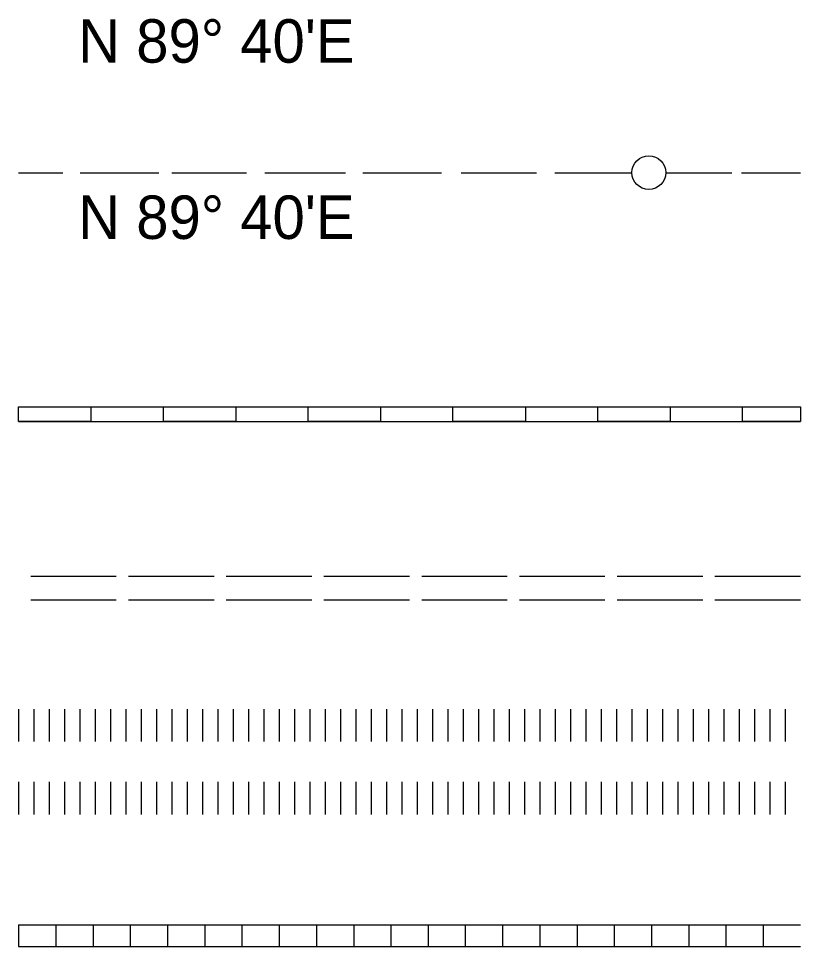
# Model space of a CAD drawing. Extents: x 49991.4 to 50021, y 49987.6 to 50011.4.
# Drawn here: x 50003.971 to 50005.051, y 49992.2 to 49993.482 of the extents above; entities that cross this region are included whole.
import ezdxf

# ---------------------------------------------------------------- set-up
doc = ezdxf.new("R2010")
doc.units = 0
doc.layers.add('Level 1', color=7, linetype='Continuous')
doc.layers.add('Level 2', color=7, linetype='Continuous')

msp = doc.modelspace()

# ---------------------------------------------------------------- linework, layer by layer
at = {"layer": 'Level 1'}
for p, q in [((50003.9708, 49993.2685), (50004.0321, 49993.2685)), ((50004.0559, 49993.2685), (50004.1647, 49993.2685)), ((50004.1826, 49993.2685), (50004.2855, 49993.2685)), ((50004.3108, 49993.2685), (50004.4226, 49993.2685)), ((50004.4464, 49993.2685), (50004.5552, 49993.2685)), ((50004.582, 49993.2685), (50004.6864, 49993.2685)), ((50004.7117, 49993.2685), (50004.818, 49993.2685)), ((50004.8647, 49993.2685), (50004.9561, 49993.2685)), ((50004.9695, 49993.2685), (50005.0508, 49993.2685)), ((50003.9708, 49992.9453), (50005.0508, 49992.9453)), ((50003.9708, 49992.9253), (50005.0508, 49992.9253)), ((50003.9877, 49992.7118), (50004.1058, 49992.7118)), ((50004.1227, 49992.7118), (50004.2408, 49992.7118)), ((50004.2577, 49992.7118), (50004.3758, 49992.7118)), ((50004.3927, 49992.7118), (50004.5108, 49992.7118)), ((50004.5277, 49992.7118), (50004.6458, 49992.7118)), ((50004.6627, 49992.7118), (50004.7808, 49992.7118)), ((50004.7977, 49992.7118), (50004.9158, 49992.7118)), ((50004.9327, 49992.7118), (50005.0508, 49992.7118)), ((50003.9877, 49992.6788), (50004.1058, 49992.6788)), ((50004.1227, 49992.6788), (50004.2408, 49992.6788)), ((50004.2577, 49992.6788), (50004.3758, 49992.6788)), ((50004.3927, 49992.6788), (50004.5108, 49992.6788)), ((50004.5277, 49992.6788), (50004.6458, 49992.6788)), ((50004.6627, 49992.6788), (50004.7808, 49992.6788)), ((50004.7977, 49992.6788), (50004.9158, 49992.6788)), ((50004.9327, 49992.6788), (50005.0508, 49992.6788)), ((50003.9708, 49992.5281), (50003.9708, 49992.4831)), ((50003.992, 49992.5281), (50003.992, 49992.4831)), ((50004.0131, 49992.5281), (50004.0131, 49992.4831)), ((50004.0343, 49992.5281), (50004.0343, 49992.4831)), ((50004.0555, 49992.5281), (50004.0555, 49992.4831)), ((50004.0767, 49992.5281), (50004.0767, 49992.4831)), ((50004.0978, 49992.5281), (50004.0978, 49992.4831)), ((50004.119, 49992.5281), (50004.119, 49992.4831)), ((50004.1402, 49992.5281), (50004.1402, 49992.4831)), ((50004.1614, 49992.5281), (50004.1614, 49992.4831)), ((50004.1826, 49992.5281), (50004.1826, 49992.4831)), ((50004.2037, 49992.5281), (50004.2037, 49992.4831)), ((50004.2249, 49992.5281), (50004.2249, 49992.4831)), ((50004.2461, 49992.5281), (50004.2461, 49992.4831)), ((50004.2673, 49992.5281), (50004.2673, 49992.4831)), ((50004.2884, 49992.5281), (50004.2884, 49992.4831)), ((50004.3096, 49992.5281), (50004.3096, 49992.4831)), ((50004.3308, 49992.5281), (50004.3308, 49992.4831)), ((50004.3308, 49992.5281), (50004.3308, 49992.4831)), ((50004.352, 49992.5281), (50004.352, 49992.4831)), ((50004.3731, 49992.5281), (50004.3731, 49992.4831)), ((50004.3943, 49992.5281), (50004.3943, 49992.4831)), ((50004.4155, 49992.5281), (50004.4155, 49992.4831)), ((50004.4367, 49992.5281), (50004.4367, 49992.4831)), ((50004.4578, 49992.5281), (50004.4578, 49992.4831)), ((50004.479, 49992.5281), (50004.479, 49992.4831)), ((50004.5002, 49992.5281), (50004.5002, 49992.4831)), ((50004.5214, 49992.5281), (50004.5214, 49992.4831)), ((50004.5426, 49992.5281), (50004.5426, 49992.4831)), ((50004.5637, 49992.5281), (50004.5637, 49992.4831)), ((50004.5849, 49992.5281), (50004.5849, 49992.4831)), ((50004.6061, 49992.5281), (50004.6061, 49992.4831)), ((50004.6273, 49992.5281), (50004.6273, 49992.4831)), ((50004.6484, 49992.5281), (50004.6484, 49992.4831)), ((50004.6696, 49992.5281), (50004.6696, 49992.4831)), ((50004.6908, 49992.5281), (50004.6908, 49992.4831)), ((50004.6908, 49992.5281), (50004.6908, 49992.4831)), ((50004.712, 49992.5281), (50004.712, 49992.4831)), ((50004.7331, 49992.5281), (50004.7331, 49992.4831)), ((50004.7543, 49992.5281), (50004.7543, 49992.4831)), ((50004.7755, 49992.5281), (50004.7755, 49992.4831)), ((50004.7967, 49992.5281), (50004.7967, 49992.4831)), ((50004.8178, 49992.5281), (50004.8178, 49992.4831)), ((50004.839, 49992.5281), (50004.839, 49992.4831)), ((50004.8602, 49992.5281), (50004.8602, 49992.4831)), ((50004.8814, 49992.5281), (50004.8814, 49992.4831)), ((50004.9026, 49992.5281), (50004.9026, 49992.4831)), ((50004.9237, 49992.5281), (50004.9237, 49992.4831)), ((50004.9449, 49992.5281), (50004.9449, 49992.4831)), ((50004.9661, 49992.5281), (50004.9661, 49992.4831)), ((50004.9873, 49992.5281), (50004.9873, 49992.4831)), ((50005.0084, 49992.5281), (50005.0084, 49992.4831)), ((50005.0296, 49992.5281), (50005.0296, 49992.4831)), ((50003.9708, 49992.4276), (50003.9708, 49992.3826)), ((50003.992, 49992.4276), (50003.992, 49992.3826)), ((50004.0131, 49992.4276), (50004.0131, 49992.3826)), ((50004.0343, 49992.4276), (50004.0343, 49992.3826)), ((50004.0555, 49992.4276), (50004.0555, 49992.3826)), ((50004.0767, 49992.4276), (50004.0767, 49992.3826)), ((50004.0978, 49992.4276), (50004.0978, 49992.3826)), ((50004.119, 49992.4276), (50004.119, 49992.3826)), ((50004.1402, 49992.4276), (50004.1402, 49992.3826)), ((50004.1614, 49992.4276), (50004.1614, 49992.3826)), ((50004.1826, 49992.4276), (50004.1826, 49992.3826)), ((50004.2037, 49992.4276), (50004.2037, 49992.3826)), ((50004.2249, 49992.4276), (50004.2249, 49992.3826)), ((50004.2461, 49992.4276), (50004.2461, 49992.3826)), ((50004.2673, 49992.4276), (50004.2673, 49992.3826)), ((50004.2884, 49992.4276), (50004.2884, 49992.3826)), ((50004.3096, 49992.4276), (50004.3096, 49992.3826)), ((50004.3308, 49992.4276), (50004.3308, 49992.3826)), ((50004.3308, 49992.4276), (50004.3308, 49992.3826)), ((50004.352, 49992.4276), (50004.352, 49992.3826)), ((50004.3731, 49992.4276), (50004.3731, 49992.3826)), ((50004.3943, 49992.4276), (50004.3943, 49992.3826)), ((50004.4155, 49992.4276), (50004.4155, 49992.3826)), ((50004.4367, 49992.4276), (50004.4367, 49992.3826)), ((50004.4578, 49992.4276), (50004.4578, 49992.3826)), ((50004.479, 49992.4276), (50004.479, 49992.3826)), ((50004.5002, 49992.4276), (50004.5002, 49992.3826)), ((50004.5214, 49992.4276), (50004.5214, 49992.3826)), ((50004.5426, 49992.4276), (50004.5426, 49992.3826)), ((50004.5637, 49992.4276), (50004.5637, 49992.3826)), ((50004.5849, 49992.4276), (50004.5849, 49992.3826)), ((50004.6061, 49992.4276), (50004.6061, 49992.3826)), ((50004.6273, 49992.4276), (50004.6273, 49992.3826)), ((50004.6484, 49992.4276), (50004.6484, 49992.3826)), ((50004.6696, 49992.4276), (50004.6696, 49992.3826)), ((50004.6908, 49992.4276), (50004.6908, 49992.3826)), ((50004.6908, 49992.4276), (50004.6908, 49992.3826)), ((50004.712, 49992.4276), (50004.712, 49992.3826)), ((50004.7331, 49992.4276), (50004.7331, 49992.3826)), ((50004.7543, 49992.4276), (50004.7543, 49992.3826)), ((50004.7755, 49992.4276), (50004.7755, 49992.3826)), ((50004.7967, 49992.4276), (50004.7967, 49992.3826)), ((50004.8178, 49992.4276), (50004.8178, 49992.3826)), ((50004.839, 49992.4276), (50004.839, 49992.3826)), ((50004.8602, 49992.4276), (50004.8602, 49992.3826)), ((50004.8814, 49992.4276), (50004.8814, 49992.3826)), ((50004.9026, 49992.4276), (50004.9026, 49992.3826)), ((50004.9237, 49992.4276), (50004.9237, 49992.3826)), ((50004.9449, 49992.4276), (50004.9449, 49992.3826)), ((50004.9661, 49992.4276), (50004.9661, 49992.3826)), ((50004.9873, 49992.4276), (50004.9873, 49992.3826)), ((50005.0084, 49992.4276), (50005.0084, 49992.3826)), ((50005.0296, 49992.4276), (50005.0296, 49992.3826)), ((50003.9708, 49992.2303), (50003.9708, 49992.2003)), ((50003.9708, 49992.2303), (50005.0508, 49992.2303)), ((50004.0222, 49992.2303), (50004.0222, 49992.2003)), ((50004.0737, 49992.2303), (50004.0737, 49992.2003)), ((50004.1251, 49992.2303), (50004.1251, 49992.2003)), ((50004.1765, 49992.2303), (50004.1765, 49992.2003)), ((50004.2279, 49992.2303), (50004.2279, 49992.2003)), ((50004.2794, 49992.2303), (50004.2794, 49992.2003)), ((50004.3308, 49992.2303), (50004.3308, 49992.2003)), ((50004.3308, 49992.2303), (50004.3308, 49992.2003)), ((50004.3822, 49992.2303), (50004.3822, 49992.2003)), ((50004.4337, 49992.2303), (50004.4337, 49992.2003)), ((50004.4851, 49992.2303), (50004.4851, 49992.2003)), ((50004.5365, 49992.2303), (50004.5365, 49992.2003)), ((50004.5879, 49992.2303), (50004.5879, 49992.2003)), ((50004.6394, 49992.2303), (50004.6394, 49992.2003)), ((50004.6908, 49992.2303), (50004.6908, 49992.2003)), ((50004.6908, 49992.2303), (50004.6908, 49992.2003)), ((50004.7422, 49992.2303), (50004.7422, 49992.2003)), ((50004.7937, 49992.2303), (50004.7937, 49992.2003)), ((50004.8451, 49992.2303), (50004.8451, 49992.2003)), ((50004.8965, 49992.2303), (50004.8965, 49992.2003)), ((50004.9479, 49992.2303), (50004.9479, 49992.2003)), ((50004.9994, 49992.2303), (50004.9994, 49992.2003)), ((50003.9708, 49992.2003), (50005.0508, 49992.2003))]:
    msp.add_line(p, q, dxfattribs=at)
for points in [[(50003.9708, 49992.9453), (50004.0708, 49992.9453), (50004.0708, 49992.9253), (50003.9708, 49992.9253)], [(50004.1708, 49992.9453), (50004.2708, 49992.9453), (50004.2708, 49992.9253), (50004.1708, 49992.9253)], [(50004.3708, 49992.9453), (50004.4708, 49992.9453), (50004.4708, 49992.9253), (50004.3708, 49992.9253)], [(50004.5708, 49992.9453), (50004.6708, 49992.9453), (50004.6708, 49992.9253), (50004.5708, 49992.9253)], [(50004.7708, 49992.9453), (50004.8708, 49992.9453), (50004.8708, 49992.9253), (50004.7708, 49992.9253)], [(50004.9708, 49992.9453), (50005.0508, 49992.9453), (50005.0508, 49992.9253), (50004.9708, 49992.9253)]]:
    msp.add_lwpolyline(points, close=True, dxfattribs=at)
msp.add_circle((50004.8414, 49993.2689), 0.0233, dxfattribs=at)

# ---------------------------------------------------------------- texts
at = {"layer": 'Level 2'}
for p in [(50004.0531, 49993.4207), (50004.0531, 49993.1773)]:
    msp.add_text("N 89° 40'E", height=0.06, dxfattribs=at).set_placement(p)

doc.saveas('drawing.dxf')
